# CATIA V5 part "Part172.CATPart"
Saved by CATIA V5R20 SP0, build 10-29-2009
Part number: FA 126700-3
Revision: ANY
Definition: UNKNOWN
Nomenclature: FA 126700-3
Source: Unknown
Bounding box of the stored display mesh (mm): x -3.264 to 3.264, y -2.475 to 2.475, z -3 to 3
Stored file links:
  C:\Users\Utente\Desktop\IO LAVORO\3D X SITO CF\CUMSA\3D files FA\FA 126708-20\Part172.CATPart
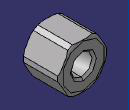
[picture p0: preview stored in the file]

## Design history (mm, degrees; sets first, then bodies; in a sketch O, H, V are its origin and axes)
Body1 "Chaflán4" (main body)
  Solid1: solid without history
